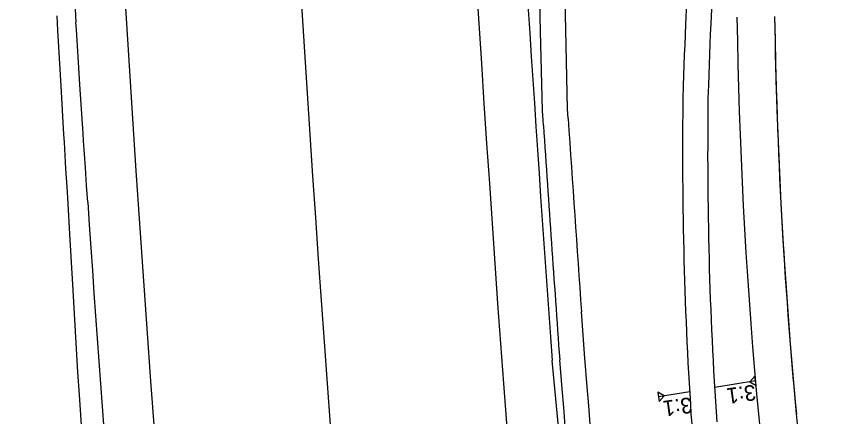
# Model space of a CAD drawing. Extents: x 2957411 to 5201395, y -5659629 to 3720102.
# Drawn here: x 5196705.2 to 5197033.5, y 3711932.7 to 3712091.8 of the extents above; entities that cross this region are included whole.
import ezdxf

# ---------------------------------------------------------------- set-up
doc = ezdxf.new("R2010")
doc.units = 0
for name, color, linetype in [('Default', 7, 'Continuous'), ('dsnProfileGradePropLine', 7, 'Continuous'), ('TES', 7, 'Continuous'), ('TL_Backslope', 7, 'Continuous')]:
    doc.layers.add(name, color=color, linetype=linetype)

msp = doc.modelspace()

# ---------------------------------------------------------------- linework, layer by layer
at = {"layer": 'Default'}
msp.add_arc((5212287.92, 3713070.59), 15500, 180.861376, 188.68311, dxfattribs=at)
at = {"layer": 'dsnProfileGradePropLine'}
for centre, radius, start, end in [((5212287.92, 3713070.59), 15500, 180.861376, 188.68311), ((5212287.92, 3713070.59), 15500, 180.861376, 188.68311), ((5212287.92, 3713070.59), 15500, 180.861376, 188.68311), ((5212287.92, 3713070.59), 15500, 180.861376, 188.68311), ((5199006.68, 3712121.83), 2000, 180.86138, 189.39805), ((5199006.68, 3712121.83), 2000, 180.86138, 189.39805), ((5199006.68, 3712121.83), 2000, 180.86138, 189.39805), ((5199006.68, 3712121.83), 2000, 180.86138, 185.40217), ((5199006.68, 3712121.83), 2000, 180.86138, 189.39805)]:
    msp.add_arc(centre, radius, start, end, dxfattribs=at)
at = {"layer": 'TES'}
for p, q in [((5196999.3, 3711946.85), (5196983.12, 3711944.17)), ((5196973.21, 3711942.53), (5196960.72, 3711940.47))]:
    msp.add_line(p, q, dxfattribs=at)
for points in [[(5196974.03, 3711929.61), (5196973.76, 3711933.68), (5196973.5, 3711937.76), (5196973.25, 3711941.84), (5196973.01, 3711945.92), (5196972.78, 3711949.99), (5196972.56, 3711954.07), (5196972.35, 3711958.15), (5196972.15, 3711962.23), (5196971.96, 3711966.31), (5196971.79, 3711970.39), (5196971.62, 3711974.47), (5196971.47, 3711978.55), (5196971.32, 3711982.63), (5196971.19, 3711986.71), (5196971.06, 3711990.79), (5196970.95, 3711994.87), (5196970.85, 3711998.95), (5196970.76, 3712003.03), (5196970.68, 3712007.11), (5196970.6, 3712011.19), (5196970.54, 3712015.28), (5196970.5, 3712019.35), (5196970.46, 3712023.43), (5196970.43, 3712027.51), (5196970.41, 3712031.59), (5196970.4, 3712035.67), (5196970.4, 3712039.75), (5196970.41, 3712043.83), (5196970.43, 3712047.91), (5196970.47, 3712054.03), (5196970.51, 3712058.82), (5196970.68, 3712064.22), (5196970.81, 3712068.3), (5196970.95, 3712072.38), (5196971.1, 3712076.46), (5196971.25, 3712080.53), (5196971.42, 3712084.61), (5196971.59, 3712088.68), (5196974.71, 3712156.78)], [(5196974.03, 3711929.61), (5196973.76, 3711933.68), (5196973.5, 3711937.76), (5196973.25, 3711941.84), (5196973.01, 3711945.92), (5196972.78, 3711949.99), (5196972.56, 3711954.07), (5196972.35, 3711958.15), (5196972.15, 3711962.23), (5196971.96, 3711966.31), (5196971.79, 3711970.39), (5196971.62, 3711974.47), (5196971.47, 3711978.55), (5196971.32, 3711982.63), (5196971.19, 3711986.71), (5196971.06, 3711990.79), (5196970.95, 3711994.87), (5196970.85, 3711998.95), (5196970.76, 3712003.03), (5196970.68, 3712007.11), (5196970.6, 3712011.19), (5196970.54, 3712015.28), (5196970.5, 3712019.35), (5196970.46, 3712023.43), (5196970.43, 3712027.51), (5196970.41, 3712031.59), (5196970.4, 3712035.67), (5196970.4, 3712039.75), (5196970.41, 3712043.83), (5196970.43, 3712047.91), (5196970.47, 3712054.03), (5196970.51, 3712058.82), (5196970.68, 3712064.22), (5196970.81, 3712068.3), (5196970.95, 3712072.38), (5196971.1, 3712076.46), (5196971.25, 3712080.53), (5196971.42, 3712084.61), (5196971.59, 3712088.68), (5196974.71, 3712156.78)], [(5196983.99, 3711930.55), (5196983.72, 3711934.61), (5196983.46, 3711938.66), (5196983.21, 3711942.72), (5196982.97, 3711946.78), (5196982.74, 3711950.83), (5196982.53, 3711954.89), (5196982.32, 3711958.95), (5196982.12, 3711963.01), (5196981.94, 3711967.07), (5196981.76, 3711971.13), (5196981.6, 3711975.19), (5196981.44, 3711979.25), (5196981.3, 3711983.31), (5196981.17, 3711987.37), (5196981.04, 3711991.43), (5196980.93, 3711995.49), (5196980.83, 3711999.55), (5196980.74, 3712003.61), (5196980.66, 3712007.67), (5196980.59, 3712011.73), (5196980.53, 3712015.8), (5196980.48, 3712019.85), (5196980.45, 3712023.91), (5196980.42, 3712027.97), (5196980.4, 3712032.03), (5196980.39, 3712036.09), (5196980.4, 3712040.15), (5196980.41, 3712044.21), (5196980.42, 3712048.27), (5196980.46, 3712054.36), (5196980.51, 3712059.13), (5196980.67, 3712064.51), (5196980.8, 3712068.57), (5196980.95, 3712072.62), (5196981.09, 3712076.68), (5196981.25, 3712080.74), (5196981.42, 3712084.79), (5196981.59, 3712088.85), (5196984.7, 3712156.93)], [(5196983.99, 3711930.55), (5196983.72, 3711934.61), (5196983.46, 3711938.66), (5196983.21, 3711942.72), (5196982.97, 3711946.78), (5196982.74, 3711950.83), (5196982.53, 3711954.89), (5196982.32, 3711958.95), (5196982.12, 3711963.01), (5196981.94, 3711967.07), (5196981.76, 3711971.13), (5196981.6, 3711975.19), (5196981.44, 3711979.25), (5196981.3, 3711983.31), (5196981.17, 3711987.37), (5196981.04, 3711991.43), (5196980.93, 3711995.49), (5196980.83, 3711999.55), (5196980.74, 3712003.61), (5196980.66, 3712007.67), (5196980.59, 3712011.73), (5196980.53, 3712015.8), (5196980.48, 3712019.85), (5196980.45, 3712023.91), (5196980.42, 3712027.97), (5196980.4, 3712032.03), (5196980.39, 3712036.09), (5196980.4, 3712040.15), (5196980.41, 3712044.21), (5196980.42, 3712048.27), (5196980.46, 3712054.36), (5196980.51, 3712059.13), (5196980.67, 3712064.51), (5196980.8, 3712068.57), (5196980.95, 3712072.62), (5196981.09, 3712076.68), (5196981.25, 3712080.74), (5196981.42, 3712084.79), (5196981.59, 3712088.85), (5196984.7, 3712156.93)], [(5196914.91, 3712048.35), (5196914.76, 3712050.57), (5196914.49, 3712054.37), (5196913.77, 3712085.8), (5196913.39, 3712104.1)], [(5196924.74, 3712051.23), (5196924.47, 3712055.03), (5196923.75, 3712086.44), (5196923.37, 3712104.73)], [(5196757.17, 3711590.11), (5196752.63, 3711640.23), (5196750.35, 3711666.59), (5196748.35, 3711690.37), (5196744.36, 3711740.54), (5196741.9, 3711772.74), (5196740.57, 3711790.72), (5196736.96, 3711840.92), (5196734.49, 3711876.58), (5196734.34, 3711878.95), (5196733.54, 3711891.12), (5196730.26, 3711941.34), (5196729.63, 3711950.26), (5196727.59, 3711985.22), (5196726.4, 3712005.17), (5196725.67, 3712017.33), (5196725.27, 3712023.98), (5196724.83, 3712031.14), (5196724.22, 3712041.79), (5196724.05, 3712044.77), (5196722.88, 3712064.21), (5196722.23, 3712075.19), (5196721.61, 3712086.16), (5196721.29, 3712092.02)], [(5196733.51, 3712017.86), (5196733.06, 3712024.5), (5196732.58, 3712031.66), (5196731.87, 3712042.3), (5196731.67, 3712045.27), (5196730.41, 3712064.7), (5196729.7, 3712075.66), (5196729, 3712086.63), (5196728.82, 3712089.57)], [(5196949.02, 3711756.13), (5196948.81, 3711758.14), (5196947.25, 3711774.72), (5196946.01, 3711787.93), (5196945.71, 3711791.25), (5196944.2, 3711807.57), (5196942.74, 3711823.65), (5196941.9, 3711833.03), (5196941.28, 3711839.93), (5196939.76, 3711857.01), (5196939.29, 3711862.38), (5196938.17, 3711875.22), (5196936.51, 3711894.44), (5196936.06, 3711899.66), (5196935.48, 3711906.44), (5196934.98, 3711912.36), (5196933.54, 3711929.56), (5196932.92, 3711936.97), (5196932.3, 3711944.46), (5196931.36, 3711955.93), (5196930.03, 3711974.3)], [(5196920.83, 3711928.61), (5196918.36, 3711954.99)], [(5196923.56, 3711928.82), (5196922.95, 3711936.23), (5196922.33, 3711943.73), (5196921.38, 3711955.21)]]:
    msp.add_lwpolyline(points, dxfattribs=at)
for centre, radius, start, end in [((5212287.92, 3713070.59), 15430, 181.101919, 184.890609), ((5212287.92, 3713070.59), 15570, 181.286744, 186.220842), ((5212287.92, 3713070.6), 15590, 181.746792, 183.607835), ((5212287.92, 3713070.59), 15410, 183.042582, 184.151533), ((5199006.68, 3712121.83), 2015, 180.86138, 189.39805), ((5212287.92, 3713070.59), 15396.97, 183.796047, 184.082992), ((5212287.92, 3713070.59), 15406.97, 183.804333, 184.151533), ((5212111.4, 3713055.35), 15412.85, 183.859662, 186.012014)]:
    msp.add_arc(centre, radius, start, end, dxfattribs=at)
at = {"layer": 'TL_Backslope'}
for points in [[(5196997.08, 3711946.48), (5196999.6, 3711945), (5196998.99, 3711948.7)], [(5196962.94, 3711940.83), (5196960.41, 3711942.32), (5196961.02, 3711938.62)]]:
    msp.add_lwpolyline(points, close=True, dxfattribs=at)

# ---------------------------------------------------------------- texts
at = {"layer": 'Default'}
for p in [(5196998.98, 3711945.4), (5196973.64, 3711940.39)]:
    msp.add_text('3:1', height=6.24, rotation=187.9841, dxfattribs=at).set_placement(p)

doc.saveas('drawing.dxf')
